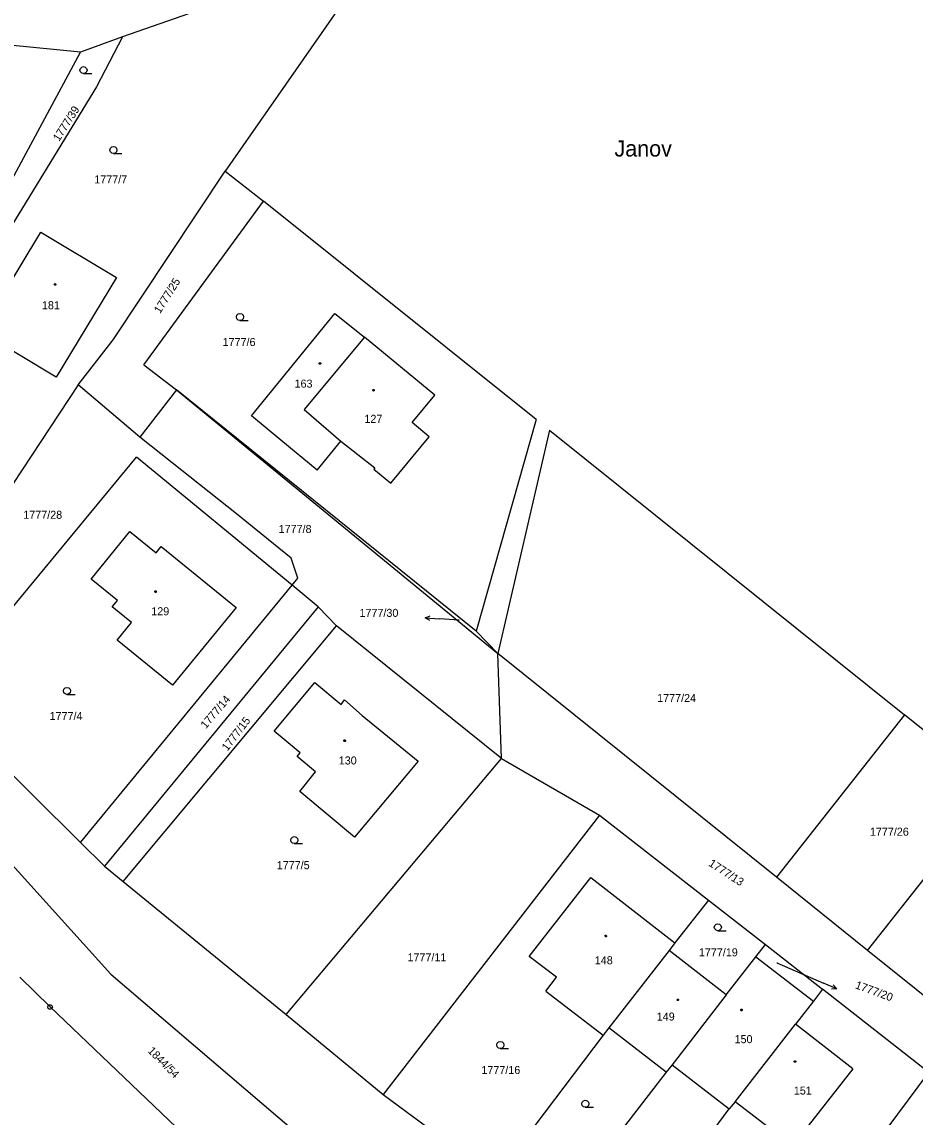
# Model space of a CAD drawing. Extents: x -747792 to -745414, y -1093712 to -1091463.
# Drawn here: x -746956.1 to -746861.7, y -1092274.2 to -1092158.4 of the extents above; entities that cross this region are included whole.
import ezdxf

# ---------------------------------------------------------------- set-up
doc = ezdxf.new("R2010")
doc.units = 0
for name, color, linetype in [('Pracovní_bod JDTM STC_VC', 7, 'Continuous'), ('Pracovní_bod JDTM STC_VC - výška', 7, 'Continuous'), ('Pracovní_bod JDTM STC_VC - číslo', 7, 'Continuous'), ('Pracovní_bod NN - výška', 7, 'Continuous'), ('Pracovní_bod polohopisu - výška', 7, 'Continuous'), ('Pracovní_bod VN - výška', 7, 'Continuous')]:
    doc.layers.add(name, color=color, linetype=linetype)

msp = doc.modelspace()

# ---------------------------------------------------------------- linework, layer by layer
at = {"layer": 'Pracovní_bod JDTM STC_VC - výška'}
for points in [[(-746952.59, -1092186.09), (-746952.54, -1092186.1), (-746952.51, -1092186.15), (-746952.5, -1092186.18), (-746952.51, -1092186.23), (-746952.55, -1092186.26), (-746952.59, -1092186.27), (-746952.64, -1092186.25), (-746952.67, -1092186.22), (-746952.68, -1092186.18), (-746952.67, -1092186.13), (-746952.62, -1092186.1)], [(-746924.61, -1092194.45), (-746924.56, -1092194.46), (-746924.53, -1092194.5), (-746924.52, -1092194.53), (-746924.53, -1092194.58), (-746924.58, -1092194.61), (-746924.61, -1092194.61), (-746924.66, -1092194.6), (-746924.69, -1092194.57), (-746924.7, -1092194.53), (-746924.69, -1092194.48), (-746924.65, -1092194.45)], [(-746918.96, -1092197.28), (-746918.91, -1092197.29), (-746918.89, -1092197.33), (-746918.88, -1092197.36), (-746918.89, -1092197.41), (-746918.93, -1092197.44), (-746918.96, -1092197.45), (-746919, -1092197.43), (-746919.03, -1092197.4), (-746919.04, -1092197.36), (-746919.03, -1092197.31), (-746918.99, -1092197.28)], [(-746941.98, -1092218.56), (-746941.93, -1092218.57), (-746941.91, -1092218.62), (-746941.9, -1092218.65), (-746941.91, -1092218.69), (-746941.95, -1092218.73), (-746941.98, -1092218.73), (-746942.02, -1092218.72), (-746942.05, -1092218.69), (-746942.07, -1092218.65), (-746942.05, -1092218.6), (-746942.01, -1092218.57)], [(-746922, -1092234.32), (-746921.95, -1092234.33), (-746921.93, -1092234.38), (-746921.92, -1092234.41), (-746921.93, -1092234.46), (-746921.97, -1092234.49), (-746922, -1092234.49), (-746922.04, -1092234.48), (-746922.08, -1092234.45), (-746922.08, -1092234.41), (-746922.08, -1092234.36), (-746922.03, -1092234.33)], [(-746894.41, -1092254.97), (-746894.36, -1092254.98), (-746894.33, -1092255.02), (-746894.33, -1092255.05), (-746894.33, -1092255.1), (-746894.38, -1092255.13), (-746894.41, -1092255.14), (-746894.46, -1092255.12), (-746894.49, -1092255.09), (-746894.5, -1092255.05), (-746894.49, -1092255.01), (-746894.45, -1092254.97)], [(-746886.81, -1092261.71), (-746886.76, -1092261.72), (-746886.74, -1092261.76), (-746886.73, -1092261.79), (-746886.74, -1092261.83), (-746886.78, -1092261.87), (-746886.81, -1092261.88), (-746886.85, -1092261.86), (-746886.89, -1092261.83), (-746886.9, -1092261.79), (-746886.89, -1092261.75), (-746886.84, -1092261.71)], [(-746880.07, -1092262.79), (-746880.02, -1092262.8), (-746879.99, -1092262.85), (-746879.98, -1092262.88), (-746879.99, -1092262.92), (-746880.03, -1092262.96), (-746880.07, -1092262.96), (-746880.11, -1092262.95), (-746880.15, -1092262.92), (-746880.16, -1092262.88), (-746880.15, -1092262.83), (-746880.1, -1092262.8)], [(-746874.42, -1092268.23), (-746874.37, -1092268.24), (-746874.34, -1092268.28), (-746874.33, -1092268.31), (-746874.34, -1092268.35), (-746874.39, -1092268.39), (-746874.42, -1092268.4), (-746874.47, -1092268.38), (-746874.5, -1092268.35), (-746874.51, -1092268.31), (-746874.5, -1092268.27), (-746874.46, -1092268.23)]]:
    msp.add_lwpolyline(points, close=True, dxfattribs=at)
at = {"layer": 'Pracovní_bod JDTM STC_VC - číslo'}
for points in [[(-746949.6, -1092163.9), (-746949.79, -1092163.85), (-746949.93, -1092163.71), (-746949.97, -1092163.52), (-746949.93, -1092163.34), (-746949.79, -1092163.2), (-746949.6, -1092163.15), (-746949.41, -1092163.2), (-746949.27, -1092163.34), (-746949.22, -1092163.52), (-746949.27, -1092163.71), (-746949.41, -1092163.85), (-746949.6, -1092163.9), (-746948.72, -1092163.9)], [(-746946.43, -1092172.34), (-746946.62, -1092172.29), (-746946.76, -1092172.15), (-746946.81, -1092171.97), (-746946.76, -1092171.78), (-746946.62, -1092171.64), (-746946.43, -1092171.59), (-746946.24, -1092171.64), (-746946.1, -1092171.78), (-746946.06, -1092171.97), (-746946.1, -1092172.15), (-746946.24, -1092172.29), (-746946.43, -1092172.34), (-746945.56, -1092172.34)], [(-746933.07, -1092189.99), (-746933.26, -1092189.94), (-746933.4, -1092189.8), (-746933.45, -1092189.61), (-746933.4, -1092189.43), (-746933.26, -1092189.29), (-746933.07, -1092189.24), (-746932.88, -1092189.29), (-746932.74, -1092189.43), (-746932.7, -1092189.61), (-746932.74, -1092189.8), (-746932.88, -1092189.94), (-746933.07, -1092189.99), (-746932.2, -1092189.99)], [(-746951.35, -1092229.52), (-746951.54, -1092229.47), (-746951.68, -1092229.33), (-746951.72, -1092229.15), (-746951.68, -1092228.96), (-746951.54, -1092228.82), (-746951.35, -1092228.77), (-746951.16, -1092228.82), (-746951.02, -1092228.96), (-746950.97, -1092229.15), (-746951.02, -1092229.33), (-746951.16, -1092229.47), (-746951.35, -1092229.52), (-746950.47, -1092229.52)], [(-746927.33, -1092245.29), (-746927.52, -1092245.24), (-746927.66, -1092245.1), (-746927.7, -1092244.92), (-746927.66, -1092244.73), (-746927.52, -1092244.59), (-746927.33, -1092244.54), (-746927.14, -1092244.59), (-746927, -1092244.73), (-746926.95, -1092244.92), (-746927, -1092245.1), (-746927.14, -1092245.24), (-746927.33, -1092245.29), (-746926.45, -1092245.29)], [(-746882.58, -1092254.5), (-746882.77, -1092254.45), (-746882.91, -1092254.31), (-746882.95, -1092254.12), (-746882.91, -1092253.94), (-746882.77, -1092253.8), (-746882.58, -1092253.75), (-746882.39, -1092253.8), (-746882.25, -1092253.94), (-746882.2, -1092254.12), (-746882.25, -1092254.31), (-746882.39, -1092254.45), (-746882.58, -1092254.5), (-746881.7, -1092254.5)], [(-746905.56, -1092266.94), (-746905.75, -1092266.89), (-746905.89, -1092266.75), (-746905.94, -1092266.56), (-746905.89, -1092266.38), (-746905.75, -1092266.24), (-746905.56, -1092266.19), (-746905.37, -1092266.24), (-746905.24, -1092266.38), (-746905.19, -1092266.56), (-746905.24, -1092266.75), (-746905.37, -1092266.89), (-746905.56, -1092266.94), (-746904.69, -1092266.94)], [(-746896.59, -1092273.16), (-746896.78, -1092273.11), (-746896.92, -1092272.97), (-746896.96, -1092272.78), (-746896.92, -1092272.6), (-746896.78, -1092272.46), (-746896.59, -1092272.41), (-746896.4, -1092272.46), (-746896.26, -1092272.6), (-746896.21, -1092272.78), (-746896.26, -1092272.97), (-746896.4, -1092273.11), (-746896.59, -1092273.16), (-746895.71, -1092273.16)]]:
    msp.add_lwpolyline(points, dxfattribs=at)
at = {"layer": 'Pracovní_bod NN - výška'}
for points in [[(-746918.07, -1092150.41), (-746945.49, -1092160)], [(-746918.07, -1092150.41), (-746934.62, -1092174.19)], [(-746945.49, -1092160), (-746948.23, -1092165.29), (-746962.05, -1092187.86), (-746971.93, -1092204.37)], [(-746949.91, -1092161.64), (-746959.95, -1092160.64)], [(-746945.49, -1092160), (-746949.91, -1092161.64)], [(-746959.95, -1092180.22), (-746949.91, -1092161.64)], [(-746946.48, -1092192.03), (-746934.62, -1092174.19)], [(-746934.62, -1092174.19), (-746930.59, -1092177.38)], [(-746943.21, -1092194.67), (-746930.59, -1092177.38)], [(-746901.79, -1092200.47), (-746930.59, -1092177.38)], [(-746960.47, -1092191.19), (-746954.11, -1092180.64)], [(-746954.11, -1092180.64), (-746946.13, -1092185.45)], [(-746946.13, -1092185.45), (-746952.49, -1092195.99)], [(-746931.84, -1092200.07), (-746923.03, -1092189.26)], [(-746923.03, -1092189.26), (-746919.92, -1092191.74)], [(-746952.49, -1092195.99), (-746960.47, -1092191.19)], [(-746919.92, -1092191.74), (-746926.27, -1092199.4)], [(-746912.48, -1092197.9), (-746919.92, -1092191.74)], [(-746950.17, -1092196.79), (-746946.48, -1092192.03)], [(-746943.21, -1092194.67), (-746939.76, -1092197.31)], [(-746950.17, -1092196.79), (-746963.07, -1092216.32)], [(-746943.65, -1092202.33), (-746950.17, -1092196.79)], [(-746939.76, -1092197.31), (-746943.65, -1092202.33)], [(-746939.76, -1092197.31), (-746905.81, -1092225.18)], [(-746908.12, -1092222.84), (-746939.76, -1092197.31)], [(-746914.87, -1092200.78), (-746912.48, -1092197.9)], [(-746926.27, -1092199.4), (-746922.4, -1092202.75)], [(-746928.76, -1092202.65), (-746931.84, -1092200.07)], [(-746913.06, -1092202.28), (-746914.87, -1092200.78)], [(-746901.79, -1092200.47), (-746908.12, -1092222.84)], [(-746940.23, -1092205.04), (-746943.65, -1092202.33)], [(-746917.12, -1092207.18), (-746913.06, -1092202.28)], [(-746900.38, -1092201.6), (-746905.81, -1092225.18)], [(-746900.38, -1092201.6), (-746862.87, -1092231.69)], [(-746924.9, -1092205.81), (-746928.76, -1092202.65)], [(-746924.9, -1092205.81), (-746922.4, -1092202.75)], [(-746922.4, -1092202.75), (-746918.82, -1092205.57)], [(-746965.16, -1092230.04), (-746943.99, -1092204.43)], [(-746927.56, -1092217.96), (-746943.99, -1092204.43)], [(-746933.45, -1092210.43), (-746940.23, -1092205.04)], [(-746918.82, -1092205.57), (-746918.92, -1092205.69)], [(-746918.92, -1092205.69), (-746917.12, -1092207.18)], [(-746927.65, -1092215.11), (-746933.45, -1092210.43)], [(-746948.79, -1092217.32), (-746944.69, -1092212.29)], [(-746944.69, -1092212.29), (-746941.93, -1092214.55)], [(-746941.93, -1092214.55), (-746941.38, -1092213.87)], [(-746941.38, -1092213.87), (-746933.48, -1092220.32)], [(-746926.96, -1092217.23), (-746927.65, -1092215.11)], [(-746946, -1092219.59), (-746948.79, -1092217.32)], [(-746927.56, -1092217.96), (-746926.96, -1092217.23)], [(-746949.9, -1092245.17), (-746927.56, -1092217.96)], [(-746924.8, -1092220.24), (-746927.56, -1092217.96)], [(-746946.56, -1092220.27), (-746946, -1092219.59)], [(-746924.8, -1092220.24), (-746947.38, -1092247.67)], [(-746944.53, -1092221.92), (-746946.56, -1092220.27)], [(-746933.48, -1092220.32), (-746940.2, -1092228.54)], [(-746922.86, -1092222.26), (-746924.8, -1092220.24)], [(-746946.04, -1092223.77), (-746944.53, -1092221.92)], [(-746945.4, -1092249.28), (-746922.86, -1092222.26)], [(-746905.43, -1092236.28), (-746922.86, -1092222.26)], [(-746908.12, -1092222.84), (-746905.81, -1092225.18)], [(-746940.2, -1092228.54), (-746946.04, -1092223.77)], [(-746876.39, -1092248.83), (-746905.81, -1092225.18)], [(-746905.43, -1092236.28), (-746905.81, -1092225.18)], [(-746929.46, -1092233.39), (-746925.15, -1092228.26)], [(-746925.15, -1092228.26), (-746922.39, -1092230.57)], [(-746965.16, -1092230.04), (-746949.9, -1092245.17)], [(-746922.39, -1092230.57), (-746922.01, -1092230.1)], [(-746922.01, -1092230.1), (-746920.14, -1092231.75)], [(-746920.14, -1092231.75), (-746914.25, -1092236.58)], [(-746862.87, -1092231.69), (-746876.39, -1092248.83)], [(-746853.22, -1092239.43), (-746862.87, -1092231.69)], [(-746926.72, -1092235.68), (-746929.46, -1092233.39)], [(-746927.04, -1092236.07), (-746926.72, -1092235.68)], [(-746928.19, -1092263.34), (-746905.43, -1092236.28)], [(-746925.07, -1092237.71), (-746927.04, -1092236.07)], [(-746914.25, -1092236.58), (-746920.96, -1092244.59)], [(-746905.43, -1092236.28), (-746895.08, -1092242.27)], [(-746926.74, -1092239.76), (-746925.07, -1092237.71)], [(-746920.96, -1092244.59), (-746926.74, -1092239.76)], [(-746866.75, -1092256.58), (-746853.22, -1092239.43)], [(-746962.04, -1092242.15), (-746946.7, -1092259.07)], [(-746895.08, -1092242.27), (-746917.94, -1092271.82)], [(-746895.08, -1092242.27), (-746883.57, -1092251.25)], [(-746949.9, -1092245.17), (-746947.38, -1092247.67)], [(-746947.38, -1092247.67), (-746945.4, -1092249.28)], [(-746945.4, -1092249.28), (-746928.19, -1092263.34)], [(-746902.5, -1092257.23), (-746895.98, -1092248.86)], [(-746895.98, -1092248.86), (-746887.11, -1092255.79)], [(-746866.75, -1092256.58), (-746876.39, -1092248.83)], [(-746883.57, -1092251.25), (-746887.11, -1092255.79)], [(-746883.57, -1092251.25), (-746877.55, -1092255.96)], [(-746887.71, -1092256.58), (-746894.08, -1092264.77)], [(-746887.11, -1092255.79), (-746887.71, -1092256.58)], [(-746881.69, -1092261.28), (-746887.71, -1092256.58)], [(-746878.56, -1092257.26), (-746877.55, -1092255.96)], [(-746877.55, -1092255.96), (-746871.51, -1092260.68)], [(-746856.67, -1092264.69), (-746866.75, -1092256.58)], [(-746899.62, -1092259.4), (-746902.5, -1092257.23)], [(-746881.69, -1092261.28), (-746878.56, -1092257.26)], [(-746878.56, -1092257.26), (-746872.48, -1092261.95)], [(-746946.7, -1092259.07), (-746879.52, -1092316.53)], [(-746953.13, -1092262.55), (-746956.34, -1092259.41)], [(-746900.76, -1092260.87), (-746899.62, -1092259.4)], [(-746900.76, -1092260.87), (-746894.7, -1092265.54)], [(-746881.69, -1092261.28), (-746887.41, -1092268.67)], [(-746871.51, -1092260.68), (-746872.48, -1092261.95)], [(-746860.28, -1092269.48), (-746871.51, -1092260.68)], [(-746939.81, -1092275.27), (-746953.13, -1092262.55)], [(-746872.48, -1092261.95), (-746874.37, -1092264.37)], [(-746928.19, -1092263.34), (-746917.94, -1092271.82)], [(-746894.08, -1092264.77), (-746894.7, -1092265.54)], [(-746888.05, -1092269.46), (-746894.08, -1092264.77)], [(-746880.76, -1092272.57), (-746874.37, -1092264.37)], [(-746868.3, -1092269.09), (-746874.37, -1092264.37)], [(-746894.7, -1092265.54), (-746906.07, -1092280.56)], [(-746888.05, -1092269.46), (-746900.3, -1092285.35)], [(-746887.41, -1092268.67), (-746888.05, -1092269.46)], [(-746887.41, -1092268.67), (-746881.38, -1092273.33)], [(-746882.31, -1092299.06), (-746860.28, -1092269.48)], [(-746868.3, -1092269.09), (-746874.7, -1092277.24)], [(-746917.94, -1092271.82), (-746906.07, -1092280.56)], [(-746880.76, -1092272.57), (-746881.38, -1092273.33)], [(-746874.7, -1092277.24), (-746880.76, -1092272.57)], [(-746893.89, -1092290.23), (-746881.38, -1092273.33)]]:
    msp.add_lwpolyline(points, dxfattribs=at)
at = {"layer": 'Pracovní_bod polohopisu - výška'}
for points in [[(-746913.01, -1092221.71), (-746913.49, -1092221.42), (-746912.97, -1092221.21)], [(-746913.49, -1092221.42), (-746911.99, -1092221.53)], [(-746909.91, -1092221.68), (-746911.99, -1092221.53)], [(-746876.35, -1092257.88), (-746871.4, -1092260.03)], [(-746870.02, -1092260.63), (-746871.4, -1092260.03)], [(-746870.38, -1092260.2), (-746870.02, -1092260.63), (-746870.58, -1092260.66)]]:
    msp.add_lwpolyline(points, dxfattribs=at)
at = {"layer": 'Pracovní_bod VN - výška'}
msp.add_lwpolyline([(-746953.05, -1092262.31), (-746952.93, -1092262.41), (-746952.88, -1092262.55), (-746952.93, -1092262.7), (-746953.05, -1092262.79), (-746953.21, -1092262.79), (-746953.33, -1092262.7), (-746953.38, -1092262.55), (-746953.33, -1092262.41), (-746953.21, -1092262.31)], close=True, dxfattribs=at)
msp.add_lwpolyline([(-746953.16, -1092262.55), (-746953.1, -1092262.55)], dxfattribs=at)

# ---------------------------------------------------------------- texts
at = {"layer": 'Pracovní_bod JDTM STC_VC'}
for s, height, rotation, p in [('1777/39', 0.85, 57.4677, (-746952.18, -1092171.13)), ('1777/25', 0.85, 57.8687, (-746941.51, -1092189.32)), ('1777/30', 0.05, 332.6593, (-746910.03, -1092221.62)), ('1777/14', 0.85, 49.6754, (-746936.67, -1092233.2)), ('1777/15', 0.85, 52.7694, (-746934.39, -1092235.57)), ('1777/13', 0.85, 326.8724, (-746883.63, -1092247.57)), ('1844/54', 0.85, 314.8403, (-746942.88, -1092267.25))]:
    msp.add_text(s, height=height, rotation=rotation, dxfattribs=at).set_placement(p)
for s, height, p in [('1777/7', 0.85, (-746948.46, -1092175.5)), ('181', 0.85, (-746953.99, -1092188.8)), ('1777/6', 0.85, (-746934.9, -1092192.69)), ('163', 0.85, (-746927.3, -1092197.09)), ('127', 0.85, (-746919.92, -1092200.81)), ('1777/28', 0.85, (-746955.96, -1092210.95)), ('1777/8', 0.85, (-746928.98, -1092212.45)), ('129', 0.85, (-746942.44, -1092221.15)), ('1777/24', 0.85, (-746888.99, -1092230.32)), ('1777/4', 0.85, (-746953.18, -1092232.22)), ('130', 0.85, (-746922.63, -1092236.92)), ('1777/26', 0.85, (-746866.51, -1092244.45)), ('1777/5', 0.85, (-746929.18, -1092247.99)), ('1777/19', 0.85, (-746884.58, -1092257.2)), ('1777/11', 0.85, (-746915.37, -1092257.73)), ('148', 0.85, (-746895.58, -1092258.04)), ('1777/20', 0.05, (-746876.48, -1092257.88)), ('149', 0.85, (-746889.03, -1092263.99)), ('150', 0.85, (-746880.81, -1092266.38)), ('1777/16', 0.85, (-746907.56, -1092269.64)), ('151', 0.85, (-746874.55, -1092271.81))]:
    msp.add_text(s, height=height, dxfattribs=at).set_placement(p)
at = {"layer": 'Pracovní_bod polohopisu - výška'}
for s, height, p in [('Janov', 1.7, (-746893.5, -1092172.66)), ('1777/30', 0.85, (-746920.44, -1092221.32))]:
    msp.add_text(s, height=height, dxfattribs=at).set_placement(p)
msp.add_text('1777/20', height=0.85, rotation=339.8786, dxfattribs=at).set_placement((-746868.13, -1092260.56))

doc.saveas('drawing.dxf')
